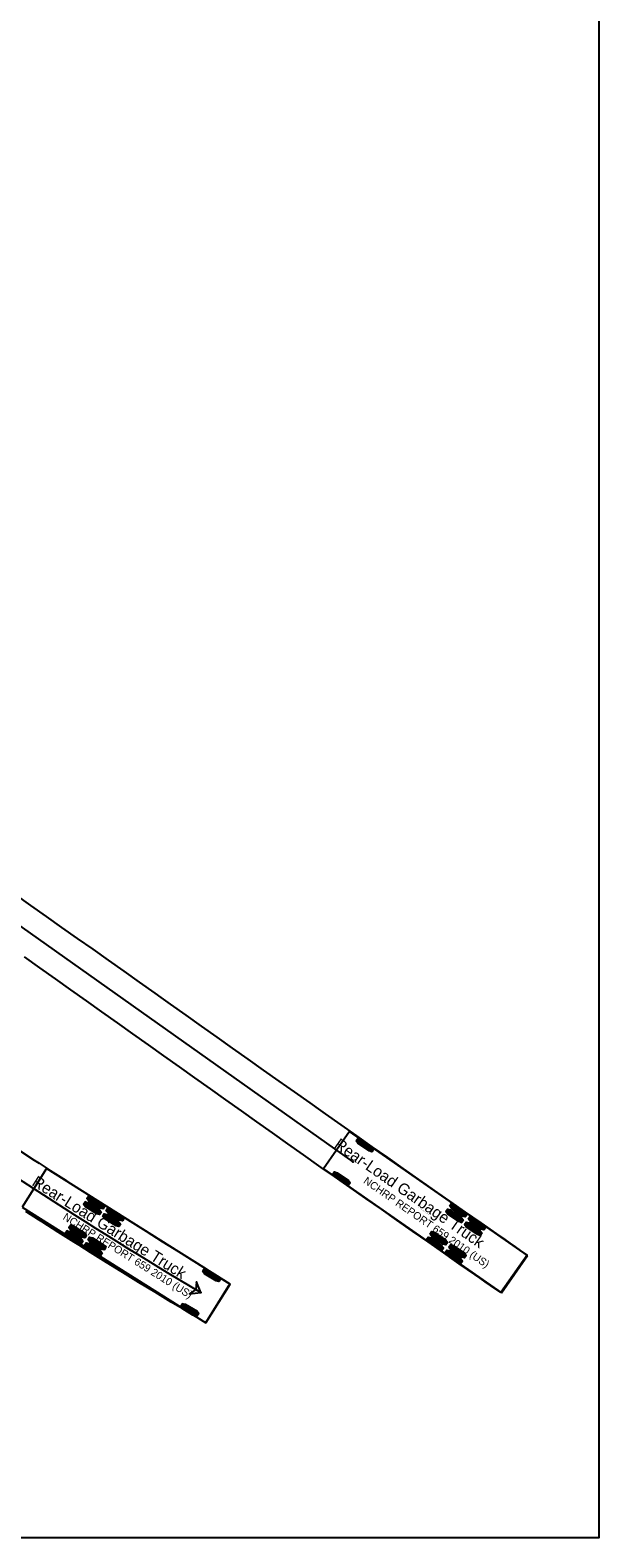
# Model space of a CAD drawing. Extents: x 973688 to 979179, y 703586 to 707602.
# Drawn here: x 978098.7 to 978198.5, y 704205.4 to 704469.8 of the extents above; entities that cross this region are included whole.
import ezdxf

# ---------------------------------------------------------------- set-up
doc = ezdxf.new("R2010")
doc.units = 0
for name, color, linetype in [('NB Right', 7, 'Continuous'), ('NO PLOT', 7, 'Continuous'), ('SB Left', 7, 'Continuous')]:
    doc.layers.add(name, color=color, linetype=linetype)

msp = doc.modelspace()

# ---------------------------------------------------------------- linework, layer by layer
at = {"layer": 'NB Right'}
for p, q in [((978155.39, 704271.36), (978046.78, 704348.26)), ((978154.74, 704276.69), (978150.17, 704270.12)), ((978185.99, 704254.93), (978154.74, 704276.69)), ((978156.19, 704275.42), (978158.92, 704273.52)), ((978155.95, 704275.08), (978158.69, 704273.18)), ((978156.07, 704275.25), (978158.8, 704273.35)), ((978150.17, 704270.12), (978181.42, 704248.37)), ((978150.17, 704270.12), (978150.17, 704270.12)), ((978151.85, 704269.2), (978154.59, 704267.3)), ((978151.97, 704269.37), (978154.71, 704267.47)), ((978152.09, 704269.54), (978154.83, 704267.64)), ((978171.7, 704262.7), (978174.43, 704260.79)), ((978171.82, 704262.87), (978174.55, 704260.96)), ((978171.94, 704263.04), (978174.67, 704261.14)), ((978172.36, 704263.66), (978175.1, 704261.75)), ((978172.48, 704263.83), (978175.22, 704261.92)), ((978172.6, 704264), (978175.34, 704262.09)), ((978174.98, 704260.41), (978177.72, 704258.51)), ((978175.1, 704260.58), (978177.83, 704258.68)), ((978175.22, 704260.75), (978177.95, 704258.85)), ((978175.65, 704261.37), (978178.38, 704259.47)), ((978175.77, 704261.54), (978178.5, 704259.64)), ((978175.88, 704261.71), (978178.62, 704259.81)), ((978168.27, 704257.77), (978171, 704255.87)), ((978168.39, 704257.94), (978171.12, 704256.04)), ((978168.51, 704258.12), (978171.24, 704256.21)), ((978168.94, 704258.73), (978171.67, 704256.83)), ((978169.05, 704258.9), (978171.79, 704257)), ((978169.17, 704259.07), (978171.91, 704257.17)), ((978172.46, 704256.79), (978175.19, 704254.88)), ((978171.55, 704255.49), (978174.29, 704253.58)), ((978171.67, 704255.66), (978174.41, 704253.75)), ((978171.79, 704255.83), (978174.53, 704253.93)), ((978172.22, 704256.45), (978174.95, 704254.54)), ((978172.34, 704256.62), (978175.07, 704254.71)), ((978181.42, 704248.37), (978185.99, 704254.93))]:
    msp.add_line(p, q, dxfattribs=at)
for points in [[(978096.08, 704318.25), (978098.8, 704316.33), (978101.52, 704314.4), (978104.24, 704312.48), (978106.97, 704310.55), (978109.69, 704308.63), (978112.41, 704306.7), (978115.13, 704304.78), (978117.85, 704302.85), (978120.57, 704300.93), (978121.66, 704300.16), (978123.29, 704299), (978126.01, 704297.08), (978128.73, 704295.15), (978131.45, 704293.23), (978134.18, 704291.3), (978136.9, 704289.38), (978139.62, 704287.46), (978142.34, 704285.53), (978145.06, 704283.61), (978147.79, 704281.69), (978149.69, 704280.35), (978150.51, 704279.77), (978153.23, 704277.85), (978155.96, 704275.93), (978158.68, 704274.01), (978161.41, 704272.1), (978164.13, 704270.18), (978166.86, 704268.27), (978168.22, 704267.32), (978169.59, 704266.36), (978172.32, 704264.45), (978175.05, 704262.55), (978177.78, 704260.64), (978180.52, 704258.74), (978181.98, 704257.72), (978182.89, 704257.09), (978183.8, 704256.45), (978184.71, 704255.82), (978185.62, 704255.19), (978185.9, 704254.99), (978181.33, 704248.43)], [(978181.33, 704248.43), (978180.41, 704249.06), (978179.5, 704249.69), (978178.58, 704250.32), (978177.67, 704250.96), (978176.76, 704251.59), (978174.02, 704253.49), (978173.2, 704254.06), (978171.28, 704255.4), (978168.55, 704257.31), (978165.82, 704259.22), (978163.08, 704261.13), (978160.34, 704263.04), (978157.6, 704264.95), (978154.87, 704266.85), (978152.13, 704268.76), (978150.21, 704270.09), (978149.4, 704270.67), (978146.68, 704272.6), (978143.96, 704274.53), (978141.24, 704276.46), (978138.52, 704278.39), (978135.8, 704280.31), (978133.08, 704282.24), (978130.36, 704284.17), (978127.64, 704286.1), (978124.92, 704288.02), (978122.2, 704289.95), (978119.48, 704291.88), (978116.76, 704293.81), (978114.04, 704295.73), (978111.32, 704297.66), (978108.6, 704299.59), (978105.88, 704301.51), (978103.16, 704303.44), (978100.44, 704305.37), (978097.72, 704307.29)]]:
    msp.add_lwpolyline(points, dxfattribs=at)
for points in [[(978155.92, 704275.04), (978156.22, 704275.47), (978156.69, 704275.33), (978158.66, 704273.96), (978158.95, 704273.56), (978158.66, 704273.14), (978158.18, 704273.27), (978156.21, 704274.65)], [(978151.83, 704269.16), (978152.12, 704269.59), (978152.6, 704269.45), (978154.56, 704268.08), (978154.86, 704267.68), (978154.56, 704267.25), (978154.09, 704267.39), (978152.12, 704268.76)], [(978171.67, 704262.66), (978171.96, 704263.08), (978172.44, 704262.94), (978174.41, 704261.57), (978174.7, 704261.18), (978174.4, 704260.75), (978173.93, 704260.89), (978171.96, 704262.26)], [(978172.33, 704263.61), (978172.63, 704264.04), (978173.1, 704263.9), (978175.07, 704262.53), (978175.37, 704262.14), (978175.07, 704261.71), (978174.6, 704261.85), (978172.63, 704263.22)], [(978174.95, 704260.37), (978175.25, 704260.8), (978175.72, 704260.66), (978177.69, 704259.29), (978177.98, 704258.89), (978177.69, 704258.47), (978177.21, 704258.6), (978175.24, 704259.97)], [(978175.62, 704261.33), (978175.91, 704261.75), (978176.39, 704261.62), (978178.36, 704260.25), (978178.65, 704259.85), (978178.35, 704259.42), (978177.88, 704259.56), (978175.91, 704260.93)], [(978168.24, 704257.73), (978168.54, 704258.16), (978169.01, 704258.02), (978170.98, 704256.65), (978171.27, 704256.25), (978170.98, 704255.83), (978170.5, 704255.96), (978168.53, 704257.34)], [(978168.91, 704258.69), (978169.2, 704259.12), (978169.68, 704258.98), (978171.65, 704257.61), (978171.94, 704257.21), (978171.64, 704256.78), (978171.17, 704256.92), (978169.2, 704258.29)], [(978172.19, 704256.4), (978172.49, 704256.83), (978172.96, 704256.69), (978174.93, 704255.32), (978175.22, 704254.93), (978174.92, 704254.5), (978174.45, 704254.64), (978172.48, 704256.01)], [(978171.52, 704255.45), (978171.82, 704255.87), (978172.29, 704255.73), (978174.26, 704254.36), (978174.56, 704253.97), (978174.26, 704253.54), (978173.79, 704253.68), (978171.82, 704255.05)]]:
    msp.add_lwpolyline(points, close=True, dxfattribs=at)
msp.add_circle((978155.39, 704271.36), 0.0417, dxfattribs=at)
at = {"layer": 'NO PLOT'}
msp.add_lwpolyline([(977518.51, 704645.43), (978198.51, 704645.43), (978198.51, 704205.43), (977518.51, 704205.43)], close=True, dxfattribs=at)
at = {"layer": 'SB Left'}
for p, q in [((978101.57, 704270.19), (978097.32, 704263.41)), ((978133.81, 704249.92), (978101.57, 704270.19)), ((978111.54, 704263.18), (978108.72, 704264.96)), ((978111.65, 704263.36), (978108.83, 704265.13)), ((978111.76, 704263.54), (978108.94, 704265.31)), ((978097.32, 704263.41), (978129.56, 704243.15)), ((978110.92, 704262.19), (978108.1, 704263.97)), ((978111.03, 704262.37), (978108.21, 704264.14)), ((978111.14, 704262.55), (978108.32, 704264.32)), ((978114.53, 704260.42), (978111.71, 704262.19)), ((978114.93, 704261.05), (978112.11, 704262.83)), ((978115.04, 704261.23), (978112.22, 704263)), ((978115.15, 704261.41), (978112.33, 704263.18)), ((978108.35, 704258.1), (978105.53, 704259.88)), ((978108.46, 704258.28), (978105.64, 704260.05)), ((978108.57, 704258.46), (978105.75, 704260.23)), ((978114.31, 704260.07), (978111.49, 704261.84)), ((978114.42, 704260.24), (978111.6, 704262.02)), ((978107.73, 704257.11), (978104.91, 704258.89)), ((978107.84, 704257.29), (978105.02, 704259.06)), ((978107.95, 704257.47), (978105.13, 704259.24)), ((978111.12, 704254.99), (978108.29, 704256.76)), ((978111.23, 704255.16), (978108.4, 704256.94)), ((978111.34, 704255.34), (978108.51, 704257.11)), ((978111.74, 704255.97), (978108.91, 704257.75)), ((978111.85, 704256.15), (978109.02, 704257.92)), ((978111.96, 704256.33), (978109.14, 704258.1)), ((978131.88, 704250.45), (978129.02, 704252.16)), ((978131.99, 704250.63), (978129.12, 704252.33)), ((978132.09, 704250.81), (978129.23, 704252.51)), ((978129.56, 704243.15), (978133.81, 704249.92)), ((978133.81, 704249.92), (978133.81, 704249.92)), ((978128.19, 704244.55), (978125.33, 704246.26)), ((978128.29, 704244.73), (978125.43, 704246.44)), ((978128.08, 704244.37), (978125.22, 704246.08))]:
    msp.add_line(p, q, dxfattribs=at)
for points in [[(978096.67, 704273.47), (978099.45, 704271.66), (978100.29, 704271.11), (978102.24, 704269.85), (978105.03, 704268.06), (978105.31, 704267.88), (978107.83, 704266.27), (978110.07, 704264.85), (978110.63, 704264.49), (978113.45, 704262.72), (978116.26, 704260.95), (978119.09, 704259.18), (978121.91, 704257.4), (978124.74, 704255.63), (978127.55, 704253.86), (978129.61, 704252.57), (978130.54, 704251.98), (978131.48, 704251.39), (978132.4, 704250.81), (978133.32, 704250.23), (978133.77, 704249.95), (978129.52, 704243.18), (978129.15, 704243.39), (978128.22, 704243.94), (978127.28, 704244.5), (978126.33, 704245.07), (978125.38, 704245.64), (978123.49, 704246.77), (978122.07, 704247.63), (978120.64, 704248.49), (978117.8, 704250.22), (978114.96, 704251.96), (978114.68, 704252.14), (978112.12, 704253.72), (978109.29, 704255.48), (978107.31, 704256.73), (978106.46, 704257.26), (978103.63, 704259.05), (978100.81, 704260.85), (978100.25, 704261.21), (978097.99, 704262.66)], [(978128.66, 704248.44), (978127.92, 704250.3), (978127.8, 704248.95), (978126.67, 704248.21), (978128.66, 704248.44)]]:
    msp.add_lwpolyline(points, dxfattribs=at)
for points in [[(978111.79, 704263.58), (978111.51, 704263.14), (978111.04, 704263.25), (978109, 704264.53), (978108.69, 704264.91), (978108.97, 704265.35), (978109.45, 704265.24), (978111.48, 704263.96)], [(978111.17, 704262.59), (978110.89, 704262.15), (978110.42, 704262.27), (978108.38, 704263.54), (978108.07, 704263.92), (978108.35, 704264.36), (978108.83, 704264.25), (978110.86, 704262.97)], [(978114.56, 704260.46), (978114.28, 704260.02), (978113.8, 704260.14), (978111.77, 704261.42), (978111.46, 704261.8), (978111.73, 704262.24), (978112.21, 704262.12), (978114.25, 704260.84)], [(978115.18, 704261.45), (978114.9, 704261.01), (978114.42, 704261.13), (978112.39, 704262.4), (978112.08, 704262.78), (978112.36, 704263.22), (978112.83, 704263.11), (978114.87, 704261.83)], [(978108.6, 704258.5), (978108.32, 704258.06), (978107.84, 704258.17), (978105.81, 704259.45), (978105.5, 704259.83), (978105.78, 704260.27), (978106.25, 704260.16), (978108.29, 704258.88)], [(978107.98, 704257.51), (978107.7, 704257.07), (978107.22, 704257.19), (978105.19, 704258.46), (978104.88, 704258.84), (978105.16, 704259.28), (978105.63, 704259.17), (978107.67, 704257.89)], [(978111.36, 704255.38), (978111.09, 704254.94), (978110.61, 704255.06), (978108.58, 704256.34), (978108.27, 704256.72), (978108.54, 704257.16), (978109.02, 704257.04), (978111.05, 704255.76)], [(978111.99, 704256.37), (978111.71, 704255.93), (978111.23, 704256.05), (978109.2, 704257.32), (978108.89, 704257.7), (978109.16, 704258.14), (978109.64, 704258.03), (978111.67, 704256.75)], [(978132.12, 704250.85), (978131.85, 704250.4), (978131.37, 704250.51), (978129.31, 704251.74), (978128.99, 704252.11), (978129.26, 704252.56), (978129.74, 704252.45), (978131.8, 704251.22)], [(978128.66, 704248.44), (978127.92, 704250.3), (978127.8, 704248.95), (978126.67, 704248.21)], [(978128.32, 704244.77), (978128.05, 704244.33), (978127.57, 704244.43), (978125.51, 704245.66), (978125.19, 704246.03), (978125.46, 704246.48), (978125.94, 704246.38), (978128, 704245.15)]]:
    msp.add_lwpolyline(points, close=True, dxfattribs=at)
msp.add_circle((978128.66, 704248.44), 0.0417, dxfattribs=at)
msp.add_arc((978621.57, 705074.45), 961.91, 230.92092, 239.17356, dxfattribs=at)

# ---------------------------------------------------------------- texts
at = {"layer": 'NB Right'}
for s, height, p in [('Rear-Load Garbage Truck', 2, (978151.91, 704273.98)), ('NCHRP REPORT 659 2010 (US)', 1.3333, (978157.08, 704267.74)), ('(c) 2022 Transoft Solutions, Inc. All rights reserved.', 0.08, (978166.71, 704263.43))]:
    msp.add_text(s, height=height, rotation=325.1549, dxfattribs=at).set_placement(p)
at = {"layer": 'SB Left'}
for s, height, p in [('Rear-Load Garbage Truck', 2, (978098.88, 704267.34)), ('NCHRP REPORT 659 2010 (US)', 1.3333, (978104.34, 704261.35)), ('(c) 2022 Transoft Solutions, Inc. All rights reserved.', 0.08, (978114.16, 704257.51))]:
    msp.add_text(s, height=height, rotation=327.8531, dxfattribs=at).set_placement(p)

doc.saveas('drawing.dxf')
